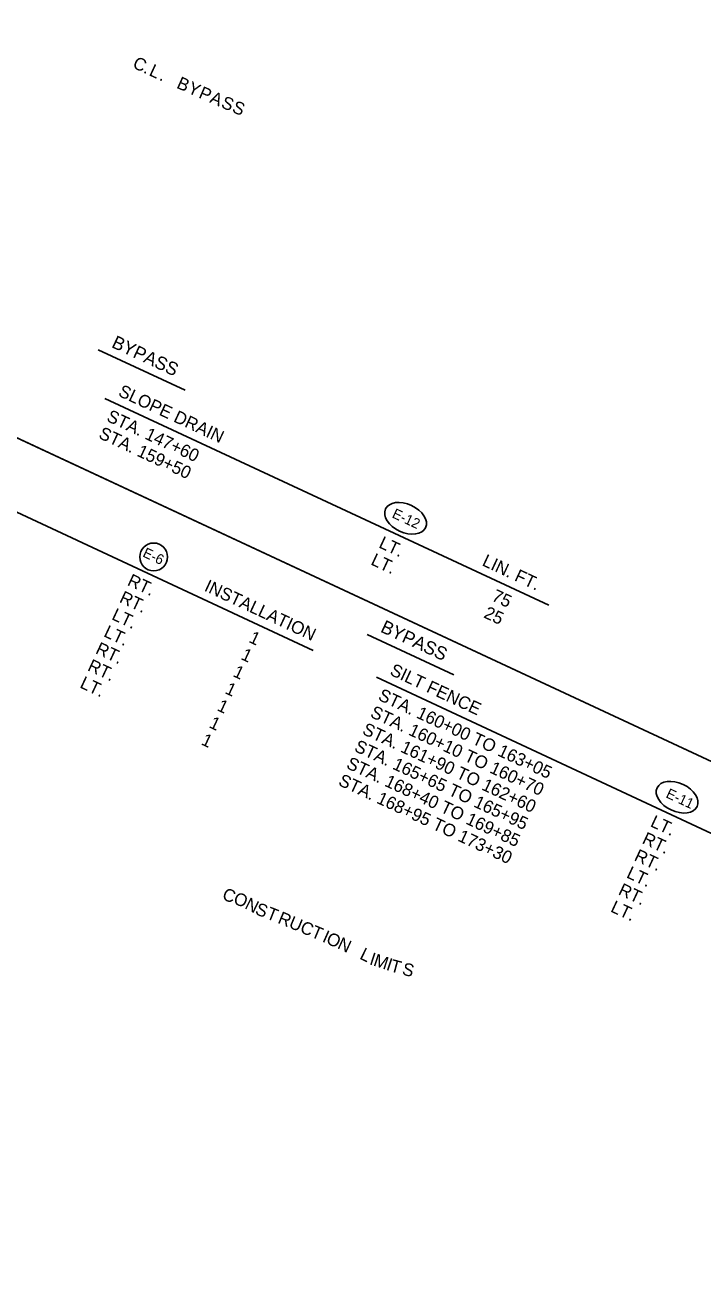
# Model space of a CAD drawing. Extents: x 980231 to 982096, y 1837566 to 1839185.
# Drawn here: x 981190 to 981512, y 1837967 to 1838566 of the extents above; entities that cross this region are included whole.
import ezdxf

# ---------------------------------------------------------------- set-up
doc = ezdxf.new("R2010")
doc.units = 0
for name, color, linetype in [('1', 7, 'Continuous'), ('44', 7, 'Continuous'), ('G-Border-Sheet', 7, 'Continuous'), ('R_Draft', 7, 'Continuous')]:
    doc.layers.add(name, color=color, linetype=linetype)

msp = doc.modelspace()

# ---------------------------------------------------------------- linework, layer by layer
at = {"layer": '1'}
msp.add_circle((981250.96, 1838313.25), 6.61, dxfattribs=at)
for centre in [(981370.69, 1838331.6), (981499.77, 1838198.98)]:
    msp.add_ellipse(centre, major_axis=(9.53, -4.45), ratio=0.638788, dxfattribs=at)
at = {"layer": '44'}
for p, q in [((981224.55, 1838411.75), (981265.86, 1838392.49)), ((981227.77, 1838388.63), (981438.75, 1838290.25)), ((981108.37, 1838370.67), (981326.79, 1838268.82)), ((981352.37, 1838276.41), (981393.68, 1838257.15)), ((981356.85, 1838256.01), (981567.84, 1838157.62))]:
    msp.add_line(p, q, dxfattribs=at)
at = {"layer": 'G-Border-Sheet'}
msp.add_line((980846.18, 1838528.31), (981586.46, 1838183.11), dxfattribs=at)
for points in [[(980671.38, 1839184.86), (981846.87, 1838636.72), (981825.93, 1838591.82), (982096.33, 1838465.73), (981897.02, 1838038.3), (981897.02, 1838038.3), (981919.96, 1838087.51), (981609.41, 1838232.32), (981586.46, 1838183.11), (980846.18, 1838528.31), (980876.72, 1838593.79), (980491.54, 1838773.4), (980461.01, 1838707.92), (980451.13, 1838712.53)], [(980671.38, 1839184.86), (981846.87, 1838636.72), (981825.93, 1838591.82), (982096.33, 1838465.73), (981897.02, 1838038.3), (981897.02, 1838038.3), (981919.96, 1838087.51), (981609.41, 1838232.32), (981586.46, 1838183.11), (980846.18, 1838528.31), (980876.72, 1838593.79), (980491.54, 1838773.4), (980461.01, 1838707.92), (980451.13, 1838712.53)], [(980671.38, 1839184.86), (981846.87, 1838636.72), (981825.93, 1838591.82), (982096.33, 1838465.73), (981897.02, 1838038.3), (981897.02, 1838038.3), (981919.96, 1838087.51), (981609.41, 1838232.32), (981586.46, 1838183.11), (980846.18, 1838528.31), (980876.72, 1838593.79), (980491.54, 1838773.4), (980461.01, 1838707.92), (980451.13, 1838712.53)], [(980671.38, 1839184.86), (981846.87, 1838636.72), (981825.93, 1838591.82), (982096.33, 1838465.73), (981897.02, 1838038.3), (981897.02, 1838038.3), (981919.96, 1838087.51), (981609.41, 1838232.32), (981586.46, 1838183.11), (980846.18, 1838528.31), (980876.72, 1838593.79), (980491.54, 1838773.4), (980461.01, 1838707.92), (980451.13, 1838712.53)], [(981897.02, 1838038.3), (981676.77, 1837565.97), (981495.51, 1837650.49), (980230.88, 1838240.2), (980451.13, 1838712.53), (980461.01, 1838707.92), (980430.47, 1838642.44), (980815.65, 1838462.83), (980846.18, 1838528.31), (981586.46, 1838183.11), (981554.64, 1838114.87), (981865.2, 1837970.06), (981897.02, 1838038.3)], [(981897.02, 1838038.3), (981676.77, 1837565.97), (981495.51, 1837650.49), (980230.88, 1838240.2), (980451.13, 1838712.53), (980461.01, 1838707.92), (980430.47, 1838642.44), (980815.65, 1838462.83), (980846.18, 1838528.31), (981586.46, 1838183.11), (981554.64, 1838114.87), (981865.2, 1837970.06), (981897.02, 1838038.3)], [(981897.02, 1838038.3), (981676.77, 1837565.97), (981495.51, 1837650.49), (980230.88, 1838240.2), (980451.13, 1838712.53), (980461.01, 1838707.92), (980430.52, 1838642.55), (980815.7, 1838462.93), (980846.18, 1838528.31), (981586.46, 1838183.11), (981554.64, 1838114.87), (981865.2, 1837970.06), (981897.02, 1838038.3)], [(981897.02, 1838038.3), (981676.77, 1837565.97), (981495.51, 1837650.49), (980230.88, 1838240.2), (980450.96, 1838712.16), (980460.84, 1838707.56), (980430.52, 1838642.55), (980815.7, 1838462.93), (980846.18, 1838528.31), (981586.46, 1838183.11), (981554.64, 1838114.87), (981865.2, 1837970.06), (981897.02, 1838038.3)], [(981865.2, 1837970.06), (981676.77, 1837565.97), (981404.39, 1837692.98), (980230.88, 1838240.2), (980450.81, 1838711.85), (980460.69, 1838707.24), (980430.52, 1838642.55), (980815.7, 1838462.93), (980846.18, 1838528.31), (981586.46, 1838183.11), (981554.64, 1838114.87)]]:
    msp.add_lwpolyline(points, close=True, dxfattribs=at)

# ---------------------------------------------------------------- texts
at = {"layer": '1'}
for s, rotation, p in [('E-12', 334.99998, (981363.9, 1838332.16)), ('E-6 ', 335, (981245.37, 1838313.56)), ('E-11', 334.99998, (981494.06, 1838199.03))]:
    msp.add_text(s, height=4.8, rotation=rotation, dxfattribs=at).set_placement(p)
at = {"layer": '44'}
for s, height, rotation, p in [('BYPASS', 6.25, 335, (981230.54, 1838413.13)), ('SLOPE DRAIN', 6, 334.99998, (981233.7, 1838390.01)), ('STA. 147+60', 6, 334.99998, (981228.14, 1838378.08)), ('STA. 159+50', 6, 334.99998, (981224.35, 1838369.97)), ('LT.', 6, 334.99998, (981357.54, 1838317.9)), ('LT.', 6, 334.99998, (981353.76, 1838309.79)), ('LIN. FT.', 6, 334.99998, (981406.68, 1838309.35)), ('RT.', 6, 334.99998, (981238.01, 1838300)), ('INSTALLATION', 6, 335, (981274.58, 1838297.3)), ('RT.', 6, 334.99998, (981234.23, 1838291.89)), ('75', 6, 334.99998, (981411.21, 1838292.69)), ('LT.', 6, 334.99998, (981230.58, 1838283.72)), ('25', 6, 334.99998, (981407.43, 1838284.58)), ('LT.', 6, 334.99998, (981226.79, 1838275.61)), ('BYPASS', 6.25, 335, (981358.36, 1838277.79)), ('RT.', 6, 334.99998, (981222.88, 1838267.56)), ('RT.', 6, 334.99998, (981219.1, 1838259.45)), ('SILT FENCE      ', 6, 334.99998, (981362.78, 1838257.38)), ('LT.', 6, 334.99998, (981215.45, 1838251.28)), ('STA. 160+00 TO 163+05', 6, 334.99998, (981357.22, 1838245.45)), ('STA. 160+10 TO 160+70', 6, 334.99998, (981353.44, 1838237.34)), ('STA. 161+90 TO 162+60', 6, 334.99998, (981349.66, 1838229.23)), ('STA. 165+65 TO 165+95', 6, 334.99998, (981345.87, 1838221.12)), ('STA. 168+40 TO 169+85', 6, 334.99998, (981342.09, 1838213.01)), ('STA. 168+95 TO 173+30', 6, 334.99998, (981338.31, 1838204.9)), ('LT.', 6, 334.99998, (981486.62, 1838185.28)), ('RT.', 6, 334.99998, (981482.71, 1838177.23)), ('RT.', 6, 334.99998, (981478.93, 1838169.12)), ('LT.', 6, 334.99998, (981475.28, 1838160.95)), ('RT.', 6, 334.99998, (981471.37, 1838152.9)), ('LT.', 6, 334.99998, (981467.71, 1838144.73))]:
    msp.add_text(s, height=height, rotation=rotation, dxfattribs=at).set_placement(p)
at = {"layer": 'R_Draft'}
for s, rotation, p in [('C', 334.74843, (981240.54, 1838546.12)), ('L', 335.17723, (981248.36, 1838542.44)), ('.', 335.03116, (981245.69, 1838543.69)), ('B', 335.89111, (981261.44, 1838536.45)), ('.', 335.44582, (981253.27, 1838540.17)), ('Y', 336.17384, (981266.64, 1838534.12)), ('P', 336.46127, (981271.94, 1838531.78)), ('A', 336.744, (981277.17, 1838529.5)), ('S', 337.03615, (981282.58, 1838527.18)), ('S', 337.31887, (981287.83, 1838524.96)), ('1', 334.99998, (981295.8, 1838272.87)), ('1', 334.99998, (981292.01, 1838264.76)), ('1', 334.99998, (981288.23, 1838256.65)), ('1', 334.99998, (981284.45, 1838248.54)), ('1', 334.99998, (981280.67, 1838240.43)), ('1', 334.99998, (981276.89, 1838232.32)), ('1', 334.99998, (981273.11, 1838224.21)), ('C', 339.28516, (981283.12, 1838150.51)), ('O', 339.28516, (981288.43, 1838148.5)), ('N', 333.37202, (981293.81, 1838146.22)), ('S', 338.50959, (981298.8, 1838143.5)), ('T', 338.50959, (981304.08, 1838141.43)), ('R', 337.43256, (981309.53, 1838139.29)), ('U', 337.43256, (981314.77, 1838137.11)), ('C', 337.38794, (981320.09, 1838134.9)), ('T', 337.38794, (981325.32, 1838132.72)), ('I', 336.07887, (981330.71, 1838130.42)), ('O', 336.07887, (981332.52, 1838129.61)), ('N', 335.22698, (981337.88, 1838127.24)), ('L', 333.8525, (981348.46, 1838122.31)), ('I', 341.74448, (981353.15, 1838119.59)), ('M', 341.74448, (981355.03, 1838118.97)), ('I', 341.74448, (981361.14, 1838116.96)), ('T', 345.10941, (981362.99, 1838116.22)), ('S', 345.10941, (981368.65, 1838114.72))]:
    msp.add_text(s, height=6, rotation=rotation, dxfattribs=at).set_placement(p)

doc.saveas('drawing.dxf')
